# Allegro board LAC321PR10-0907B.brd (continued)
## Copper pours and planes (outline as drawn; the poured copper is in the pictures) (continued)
CHRGR_VIN on TOP: 45.01,118.9 41.85,118.9 41.74,118.79 41.74,118.35 41.69,118.3 41.12,118.3 41.01,118.19 41.01,117.63 41.14,117.5 41.14,117.5 41.21,117.43 42.5,117.43 42.61,117.32 42.61,116.56 42.37,116.31 42.37,115.17 42.48,115.06 44.71,115.06 44.75,115.1 44.75,115.35 45.07,115.67 45.07,118.85
CHRGR_VIN on TOP: 28.26,58.27 26.41,58.27 26.23,58.09 26.23,57.02 26.34,56.91 27.12,56.91 27.28,56.75 27.31,56.72 27.31,55.96 27.4,55.87 28.79,55.87 29.53,56.6 29.53,57.39 29.41,57.52 28.73,57.52 28.41,57.84 28.41,58.13
CHRGR_VIN on TOP: 13.35,56.89 13.44,56.97 13.44,58.41 13.64,58.61 13.64,59.26 13.45,59.45 11.37,59.45 11.27,59.35 11.27,58.58 11.27,58.5 10.79,58.02 10.79,57.39 11.3,56.89
CHRGR_VIN on BOTTOM: 22.07,55.85 21.23,56.69 20.11,56.69 19.27,55.85 11.87,55.85 11.44,56.28 11.44,56.31 11.22,56.52 11.22,59.23 15.54,63.55 25.27,63.55 29.48,59.33 29.48,57.12 28.21,55.85
CHRGR_VIN on IN2: 50.3,136.33 48.24,134.27 48.24,131.22 49.26,130.21 49.26,119.31 55.62,112.95 55.62,108.05 55.09,107.51 52.25,107.51 50.67,109.1 50.67,112.19 48.25,114.6 44.35,114.6 43.29,115.67 43.29,138.97 47.73,143.42 71.23,143.42 71.99,142.65 71.99,140.62 71.61,140.24 58.91,140.24 56.11,137.45 56.11,136.66 55.78,136.33
CHRGR_VIN on VCC: 23.2,55.79 22.21,56.78 22.21,90.73 23.84,92.36 47.46,92.36 54.21,99.12 54.21,110.55 54.57,110.9 60.94,110.9 60.94,92.72 54.99,86.77 36.07,86.77 30.59,81.29 30.59,56.02 30.36,55.79
CORE_FB on TOP (solid shape): 193.78,149 193.78,144.56 193.91,144.43 193.91,144.03 193.83,143.95 193.71,143.95 193.61,144.05 193.61,144.23 193.24,144.6 193.24,145.11 192.64,145.7 192.64,149 192.77,149.13 193.66,149.13
CPU_B+ on TOP (solid shape): 78.73,110.14 80.53,110.14 80.91,109.76 82.28,109.76 83.04,109 85.81,109 85.96,108.85 85.96,107.73 85.71,107.48 83.93,107.48 83.75,107.66 83.75,108.19 83.57,108.36 83.04,108.36 82.25,107.58 77.83,107.58 77.32,108.09 77.32,109.89 77.58,110.14 78.72,110.14
CPU_B+ on TOP (solid shape): 73.93,102.96 73.93,102.51 74.14,102.31 77.44,102.31 77.48,102.27 77.48,101.43 77.46,101.42 77.3,101.42 77,101.11 77,100.15 77.16,99.98 77.68,99.98 77.7,99.96 77.7,99.47 77.7,99.38 77.67,99.35 74.91,99.35 74.53,98.97 74.53,96.93 74.3,96.71 66.78,96.71 66.64,96.84 66.64,99.25 66.7,99.3 69.33,99.3 69.38,99.26 69.38,98.2 69.57,98.01 71.93,98.01 72.5,98.59 72.5,102.97 72.62,103.09 73.8,103.09
CPU_B+ on TOP: 77.96,117.95 77.96,120.43 78.34,120.81 80.05,120.81 80.31,120.56 82.02,120.56 82.4,120.18 85.45,120.18 85.58,120.05 85.58,119.03 85.32,118.78 83.67,118.78 83.37,119.08 83.37,119.54 83.32,119.59 82.56,119.59 82.43,119.46 82.43,118.14 81.77,117.48 81.77,117.17 81.69,117.09 78.82,117.09
CPU_B+ on BOTTOM: 81.51,120.68 82.4,119.79 82.4,103.23 76.77,97.59 72.88,97.59 72.73,97.75 72.73,119.64 73.77,120.68
CPU_B+ on IN1: 78.34,110.27 81.77,110.27 83.04,109 85.83,109 85.96,108.87 85.96,107.86 85.71,107.6 80.24,107.6 79.86,107.98 77.83,107.98 77.58,108.24 77.58,109.51
CPU_B+ on IN1: 85.58,120.05 85.58,119.03 85.32,118.78 83.42,118.78 82.78,118.14 79.74,118.14 79.36,118.52 78.85,118.52 77.96,119.41 77.96,119.88 78.25,120.18 85.45,120.18
CPUBST1 on TOP: 83.97,103.54 82.57,103.54 82.51,103.6 82.51,104.35 82.53,104.38 83.5,104.38 83.64,104.52 84.01,104.52 84.13,104.4 84.13,103.69
CPUDRVH1 on TOP: 83.17,108.24 83.55,108.24 83.64,108.15 83.64,107.59 84.12,107.1 84.12,105.93 84.02,105.82 83.8,105.82 83.67,105.95 83.67,106.46 82.91,107.22 82.91,107.98
CPUDRVL1 on TOP: 85.32,105.7 85.26,105.76 85.26,106.65 85.32,106.71 86.59,106.71 86.85,106.46 86.85,105.82 86.72,105.7
CPUSW1 on TOP (solid shape): 89.13,113.32 89.13,110.78 88.72,110.36 88.72,108.12 88.63,108.03 88.63,107.6 88.5,107.48 86.47,107.48 86.21,107.73 86.21,108.75 85.71,109.25 83.04,109.25 82.91,109.38 82.91,110.27 83.04,110.4 86.59,110.4 87.86,111.67 87.86,113.32 88.12,113.57 88.88,113.57
DCPDSW_1P0 on TOP: 135.41,106.89 135.82,106.89 136.1,106.61 137.88,106.61 138,106.48 138,105.77 137.92,105.68 137.31,105.68 136.94,106.05 135.77,106.05 135.52,106.31 135.21,106.31 135.19,106.28 135.11,106.28 135.03,106.36 135.03,106.48 135.11,106.56 135.11,106.71 135.13,106.74 135.26,106.74
ENVDD on TOP: 174.86,103.92 174.61,103.67 173.6,103.67 173.09,104.17 172.57,104.17 172.35,103.94 172.35,103.46 172.17,103.28 171.15,103.28 171.05,103.39 171.05,104.68 172.04,105.67 173.32,105.67 174.05,104.94 174.61,104.94 174.86,104.68
GTBST1 on TOP: 83.04,115.6 83.42,115.6 83.55,115.48 83.55,114.84 83.8,114.59 83.8,113.7 83.67,113.57 83.04,113.57 82.91,113.7 82.91,115.48
GTDRVH1 on TOP: 82.66,119.41 83.17,119.41 83.29,119.29 83.29,118.52 83.55,118.27 83.55,117 83.42,116.87 82.91,116.87 82.66,117.13 82.66,118.02 82.53,118.14 82.53,119.29
GTDRVL1 on TOP: 84.69,117.89 85.07,117.89 85.33,117.64 85.33,117.11 85.33,117.11 85.98,117.11 86.21,116.87 86.21,116.37 85.96,116.11 85.45,116.11 84.56,117 84.56,117.76
GTSW1 on TOP (solid shape): 88.33,125.12 88.33,121.53 88.3,121.49 88.3,120.35 88.22,120.28 87.51,120.28 87.41,120.18 87.41,119.9 87.56,119.74 88.3,119.74 88.35,119.69 88.35,118.73 88.27,118.65 86.34,118.65 86.15,118.84 86.15,119.99 85.71,120.43 82.66,120.43 82.53,120.56 82.53,121.45 82.66,121.57 85.53,121.57 86.85,122.89 86.85,125.14 87.04,125.34 88.11,125.34
JUSBC1_GND on TOP: outline of 112 points within 0.25,23.71 11.28,37.93
JUSBC2_GND on TOP: 0.25,10.07 0.25,11.54 0.34,11.71 0.52,11.77 1.3,11.77 1.3,11.78 4.79,11.78 5.63,11.29 6.25,12.03 6.25,14.09 7.54,14.09 7.72,13.93 7.78,13.69 7.81,13.63 7.87,13.62 7.95,13.63 8,13.66 8.02,13.72 8.03,13.84 8.1,13.95 8.13,14.01 8.1,14.06 8.07,14.09 8.25,14.09 8.25,19.19 8.02,19.19 8.01,19.28 8.04,19.36 8.03,19.43 7.97,19.47 7.92,19.48 7.86,19.48 7.79,19.46 7.77,19.39 7.78,19.29 7.77,19.19 6.25,19.19 6.25,20.98 5.63,21.72 4.79,21.23 1.5,21.23 1.33,21.31 1.25,21.48 1.25,23.66 7.6,23.66 9.38,21.88 10.9,21.88 11.28,21.5 11.28,10.45 10.9,10.07
JUSBC2_GND on IN1: 11.67,13.19 10.89,13.19 10.81,13.11 10.81,11.36 10.97,11.21 13.63,11.21 13.93,11.5 13.93,13.88 13.57,14.24 12.71,14.24
LG11 on TOP: 164.32,106.08 165.21,106.08 165.33,105.95 165.33,105.19 165.21,105.06 164.32,105.06 164.06,105.32 164.06,105.82
LG11 on BOTTOM: 168.13,114.41 169.45,114.41 169.65,114.21 169.65,113.19 169.14,112.68 168.26,112.68 168.13,112.81
MIC1_L on TOP (solid shape): 20.55,13.24 20.55,12.86 20.71,12.71 20.71,12.71 20.94,12.48 20.94,11.84 20.55,11.46 19.92,11.46 19.79,11.59 19.79,12.35 19.69,12.45 19.44,12.45 19.31,12.58 19.31,12.76 19.56,13.01 19.56,13.14 19.79,13.37 20.43,13.37
MIC1_L on IN2 (solid shape): 21.44,12.23 21.44,11.59 21.19,11.34 19.92,11.34 19.16,12.1 19.16,12.86 19.41,13.11 20.55,13.11
MIC1_L on TOP: 29.64,15.73 29.76,15.73 29.81,15.67 29.81,14.81 29.84,14.78 29.84,14.22 30.08,13.98 30.08,13.37 29.95,13.24 29.6,13.24 29.42,13.42 29.42,14.28 29.55,14.41 29.55,14.68 29.6,14.72 29.6,15.69
MIC1_L on IN2: 29.9,14.27 29.9,13.75 30.03,13.62 30.03,13.34 29.93,13.24 29.57,13.24 28.92,12.59 28.23,12.59 28.11,12.71 28.11,13.37 29.09,14.35 29.83,14.35
MIC1_R on IN2 (solid shape): 22.97,14.13 22.97,12.99 22.71,12.73 21.44,12.73 21.19,12.99 21.19,13.93 21.44,13.93 21.44,13.88 21.45,13.82 21.47,13.78 21.49,13.73 21.52,13.69 21.56,13.65 21.6,13.62 21.65,13.6 21.7,13.58 21.75,13.57 21.8,13.57 21.85,13.58 21.9,13.6 21.95,13.62 21.99,13.65 22.03,13.69 22.06,13.73 22.08,13.78 22.1,13.82 22.1,13.88 22.1,13.93 22.1,13.98 22.08,14.03 22.06,14.07 22.03,14.12 21.99,14.15 21.95,14.18 21.9,14.21 21.85,14.22 21.8,14.23 21.75,14.23 21.7,14.22 21.65,14.21 21.6,14.18 21.56,14.15 21.52,14.12 21.49,14.07 21.47,14.03 21.45,13.98 21.44,13.93 21.19,13.93 21.19,14.26 21.32,14.38 22.71,14.38
MIC1_R on TOP: 30.05,15.74 30.14,15.74 30.21,15.67 30.21,14.8 30.23,14.78 30.23,14.66 30.51,14.38 30.51,13.98 30.66,13.83 30.66,13.6 30.49,13.42 30.36,13.42 30.16,13.62 30.16,14 29.95,14.21 29.95,14.83 30,14.89 30,15.69
MIC1_R on TOP: 21.19,11.46 21.06,11.59 21.06,12.61 20.94,12.73 20.81,12.73 20.68,12.86 20.68,13.37 20.81,13.5 22.08,13.5 22.46,13.11 22.46,12.86 22.33,12.73 21.82,12.73 21.7,12.61 21.7,11.72 21.44,11.46
MIC1_R on IN2: 29.7,15.65 29.83,15.78 30.74,15.78 30.97,15.55 30.97,14.64 30.84,14.51 30.84,13.7 30.64,13.5 30.28,13.5 29.95,13.83 29.95,14.92 29.7,15.17
P_AGND on TOP: 176,122.21 176.26,121.95 177.27,121.95 177.78,121.45 177.78,121 177.96,120.82 178.61,120.82 178.67,120.76 178.67,120.15 178.61,120.09 177.97,120.09 177.88,120.18 177.25,120.18 177.07,120 176.69,120 176.26,120.43 174.99,120.43 174.87,120.31 174.46,120.31 174.43,120.28 174.43,119.87 174.22,119.67 172.95,119.67 172.7,119.92 172.7,120.81 172.32,121.19 172.32,121.83 172.57,122.08 173.21,122.08 173.46,121.83 173.46,120.81 173.59,120.68 174.32,120.68 174.36,120.72 174.36,120.93 174.35,120.94 174.35,121.95 174.61,122.21
P_AGND on GND2: 166.2,115.22 160,121.42 160,126.17 162.77,128.94 169.55,128.94 177.65,120.83 177.65,119.65 173.84,115.84 173.84,115.33 173.74,115.22
P_AGND on GND3: 164.55,115.73 160.13,120.15 160.13,126.04 162.9,128.81 169.42,128.81 177.27,120.96 177.27,119.39 173.61,115.73
P_AGND_1 on IN3: 69.2,120.43 78.97,120.43 79.36,120.05 79.36,117.51 78.97,117.13 72.75,117.13 71.86,116.24 71.86,113.83 72.37,113.32 72.37,110.27 71.61,109.51 71.61,107.48 74.91,104.17 74.91,101.25 72.37,98.71 67.29,98.71 66.91,99.09 66.91,100.49 67.67,101.25 67.67,118.91
PLL_COMP1 on TOP (solid shape): 195.1,141.41 195.1,141.08 195.31,140.88 195.69,140.88 196.68,139.89 196.76,139.89 197.08,139.56 197.08,139.2 197.06,139.17 195.9,139.17 195.85,139.23 195.85,139.95 194.82,140.98 194.82,141.41 194.88,141.46 195.05,141.46
PLL_COMP2 on TOP (solid shape): 194.72,141.38 194.72,140.7 195.63,139.79 195.63,139.13 195.61,139.1 194.67,139.1 194.67,139.1 194.49,139.1 194.42,139.18 194.42,141.41 194.47,141.46 194.65,141.46
PLL_VDD on TOP (solid shape): 194.32,141.38 194.32,139.25 194.16,139.1 193.66,139.1 193.65,139.1 193.56,139.1 193.49,139.17 193.49,139.92 194.04,140.47 194.04,141.38 194.11,141.46 194.24,141.46
REG5 on BOTTOM: 171.18,124.37 170.29,124.37 167.11,121.19 167.11,120.94 167.24,120.81 167.49,120.81 170.54,123.86 171.18,123.86 171.3,123.99 171.3,124.24
REG33 on TOP: 172.45,123.22 175.88,123.22 176,123.1 176,122.46 175.88,122.33 174.99,122.33 174.86,122.46 172.45,122.46 172.32,122.59 172.32,123.1
RING2 on TOP (solid shape): 19.67,12.23 19.67,9.69 19.77,9.58 19.77,9.53 19.79,9.53 19.79,9.18 19.77,9.15 18.8,9.15 18.78,9.18 18.78,12.23 18.9,12.35 19.54,12.35
RING2 on GND1 (solid shape): 21.82,6.97 21.82,5.67 21.77,5.62 20.55,5.62 20.55,7.15 21.65,7.15
RING2 on TOP: 21.72,6.85 21.9,6.66 21.9,5.44 21.8,5.34 20.69,5.34 20.55,5.47 20.55,6.64 20.76,6.85
RING2 on IN2: 18.52,9.56 19.67,9.56 19.73,9.5 19.98,9.5 22.21,7.27 22.21,6.13 21.82,5.75 19.03,5.75 18.27,6.51 18.27,9.3
RING2 on GND4: 20.55,6.31 20.55,6.84 20.73,7.02 22.15,7.02 22.46,6.71 22.46,6.44 22.15,6.13 20.73,6.13
SASWS on TOP (solid shape): 82.02,102.78 82.02,100.36 81.26,99.6 81.26,97.32 80.75,96.81 78.85,96.81 77.7,97.95 75.2,97.95 75.12,98.03 75.12,99.05 75.16,99.09 77.7,99.09 79.36,100.74 79.36,101.89 79.61,102.14 80.75,102.14 80.88,102.27 80.88,102.78 81.13,103.03 81.77,103.03
SD_REG2 on TOP: 25.34,78.28 26.13,78.28 26.18,78.23 26.18,78.13 26.13,78.08 26.13,77.31 24.5,75.69 23.84,75.69 23.72,75.81 23.72,76.32 23.84,76.45 24.23,76.45 25.24,77.47 25.24,78.18
SLEEVE on TOP (solid shape): 22.46,12.35 22.46,11.46 22.33,11.34 22.33,11.27 22.31,11.2 22.31,11.13 22.31,10.75 22.33,10.72 22.33,10.57 22.59,10.32 22.59,9.18 22.56,9.15 21.59,9.15 21.57,9.18 21.57,11.35 21.82,11.6 21.82,12.35 21.95,12.48 22.33,12.48
SLEEVE on GND1 (solid shape): 20.3,5.62 19.08,5.62 18.78,5.93 18.78,6.84 19.08,7.15 20.3,7.15
SLEEVE on TOP: 18.9,6.76 20.17,6.76 20.43,6.51 20.43,5.48 20.2,5.25 18.94,5.25 18.78,5.41 18.78,6.64
SLEEVE on BOTTOM: 23.86,10.7 24.24,10.32 24.24,5.88 23.86,5.49 18.9,5.49 18.52,5.88 18.52,7.27 19.16,7.91 20.17,7.91 21.06,8.8 21.06,10.45 21.32,10.7
SPK_L+ on TOP: 21.04,93.15 20.98,93.21 20.98,93.78 21.06,93.87 24.03,93.87 24.13,93.77 24.9,93.77 24.95,93.83 25.51,93.83 25.52,93.81 25.52,93.03 25.49,93 24,93 23.74,93.26 22.8,93.26 22.69,93.15
SPK_L+ on IN1: 10.31,97.18 11.94,97.18 12.1,97.02 12.1,96.6 12.03,96.54 10.39,96.54 10.19,96.74 10.19,97.06
SPK_L+ on IN1: 21.56,93.76 20.85,93.76 20.09,93 20.09,92.63 20.34,92.38 20.59,92.38 21.36,93.14 21.52,93.14 21.58,93.2 21.58,93.73
SPK_L+_L on TOP (solid shape): 206.17,116.16 206.17,115.34 205.6,114.78 204.78,114.78 204.64,114.92 204.64,115.11 204.62,115.13 204.62,115.29 204.62,115.29 204.62,116.17 204.66,116.21 206.12,116.21
SPK_L+_L on TOP: 26.75,92.96 26.96,93.16 26.96,93.92 26.84,94.04 25.83,94.04 25.76,93.97 25.76,93.02 25.82,92.96
SPK_L+_L on BOTTOM: 26.75,94.05 25.5,94.05 25.39,93.94 25.39,93.07 25.56,92.9 26.73,92.9 26.87,93.04 26.87,93.94
SPK_L+_L on BOTTOM: 40.48,103.37 40.45,103.41 40.45,105.04 40.51,105.1 40.89,105.1 41.19,104.79 41.19,103.4 41.17,103.37
SPK_L+_L on GND3: 204.78,116.23 203.84,116.23 203.61,116.01 203.61,115.3 203.95,114.96 204.93,114.96 205.12,115.14 205.12,115.89
SPK_L+_L on GND3: 42.12,106.07 42.16,106.04 42.16,105.23 41.46,104.53 41.46,104.08 41.36,103.99 40.75,103.99 40.57,104.17 40.57,104.96 41.68,106.07
SPK_L- on TOP: 21,92.77 20.98,92.75 20.98,92.1 21.03,92.05 22.17,92.05 22.3,91.91 25.5,91.91 25.53,91.94 25.53,92.7 25.51,92.72 24.65,92.72 24.47,92.54 22.79,92.54 22.56,92.77
SPK_L- on IN1: 21.08,92.71 21.55,92.71 21.63,92.62 21.63,92.06 21,91.42 20.69,91.42 20.33,91.79 20.33,91.96
SPK_L- on IN1: 11.23,96.24 9.56,96.24 9.43,96.11 9.43,95.02 9.57,94.88 10.18,94.88 11.3,96 11.3,96.17
SPK_L-_L on TOP: 25.74,92.73 26.82,92.73 27.08,93 27.08,93.62 27.09,93.62 27.09,93.84 27.77,94.52 28.21,94.52 28.32,94.41 28.32,93.97 27.96,93.61 27.96,91.88 27.76,91.69 25.88,91.69 25.69,91.88 25.69,92.68
SPK_R+ on TOP (solid shape): 252.23,133.45 252.23,133.14 252.1,133.02 251.21,133.02 251.06,133.17 251.06,133.18 249.95,134.29 247.41,134.29 247.16,134.54 247.16,135.27 247.3,135.41 250.27,135.41
SPK_R+ on IN1 (solid shape): 245.51,135.41 247.42,135.41 247.47,135.36 247.47,134.69 247.37,134.59 245.27,134.59 243.34,136.53 243.34,137.13 243.37,137.17 243.75,137.17
SPK_R+ on TOP: 242.16,137.54 242.54,137.54 242.67,137.41 242.67,137.22 242.74,137.14 243.56,137.14 243.62,137.09 243.62,136.57 243.56,136.51 242.7,136.51 242.57,136.64 242.06,136.64 242.03,136.67 242.03,137.41
SPK_R+_L on TOP: 241.9,137.42 241.9,136.72 241.83,136.65 241.14,136.65 240.96,136.83 240.96,137.91 241.07,138.02 242.01,138.02 242.12,137.92 242.12,137.63
SPK_R+_L on TOP: 210.89,124.63 212.4,124.63 212.5,124.53 212.5,123.59 212.36,123.45 210.98,123.45 210.78,123.66 210.78,124.52
SPK_R+_L on BOTTOM: 241.81,138.08 239.83,138.08 239.66,137.9 239.66,137.37 239.69,137.33 242.02,137.33 242.06,137.37 242.06,137.84
SPK_R+_L on BOTTOM: 212.16,125.05 212.16,125.23 212.62,125.69 212.78,125.69 212.95,125.52 212.95,124.86 212.32,124.24 212.32,123.74 212.11,123.53 211.8,123.53 211.62,123.71 211.62,124.51
SPK_R- on TOP (solid shape): 251.09,132.89 252.1,132.89 252.36,132.63 252.36,132.25 252.1,132 250.7,132 249.54,133.16 249.53,133.16 249.46,133.24 247.38,133.24 247.23,133.38 247.23,133.93 247.4,134.1 249.87,134.1
SPK_R- on IN1 (solid shape): 245.44,134.05 247.46,134.05 247.62,133.88 247.62,133.33 247.45,133.16 244.95,133.16 243.12,134.99 243.12,135.71 243.27,135.85 243.63,135.85
SPK_R- on TOP: 242.87,135.89 243.55,135.89 243.68,135.76 243.68,133.89 243.59,133.8 242.42,133.8 242.38,133.84 242.38,135.4
SPK_R-_L on TOP: 241.42,136.52 241.89,136.52 241.89,136.52 242.53,136.52 242.68,136.37 242.68,135.91 242.23,135.46 242.23,133.83 242.2,133.8 241.36,133.8 241.14,134.01 241.14,136.24
SW4 on TOP (solid shape): 160.13,118.65 160.13,117.76 160.64,117.25 163.05,117.25 163.43,116.87 163.43,116.37 163.18,116.11 160.38,116.11 158.93,114.66 158.93,114.02 158.81,113.9 157.44,113.9 157.33,114 157.33,116.87 158.48,118.02 158.48,118.91 158.73,119.16 159.62,119.16
SW5 on TOP (solid shape): 183.75,134.02 183.75,131.24 184.41,130.58 184.41,128.67 184.17,128.43 180.57,128.43 179.94,129.07 179.08,129.07 178.8,129.34 178.8,130.08 178.92,130.21 179.43,130.21 179.69,130.46 179.69,130.97 179.81,131.1 182.35,131.1 182.73,131.48 182.73,134.02 182.86,134.15 183.62,134.15
SW6 on TOP (solid shape): 177.81,118.26 177.81,117.78 177.81,117.78 177.81,117.66 177.49,117.34 177.49,117.34 177.46,117.31 177.46,117.08 177.45,117.04 177.45,116.99 177.45,116.94 177.45,116.89 177.46,116.85 177.49,116.78 177.49,116.64 177.64,116.49 180.96,116.49 181.72,117.25 187.31,117.25 187.56,117 187.56,115.98 187.05,115.48 186.42,115.48 185.53,114.59 182.23,114.59 181.34,115.48 177.5,115.48 177.07,115.91 176.93,115.91 176.72,116.12 176.72,117.64 177.04,117.96 177.04,118.27 177.11,118.34 177.73,118.34
SW7 on TOP (solid shape): 180.07,124.75 180.07,124.74 180.15,124.66 180.15,121.89 180.09,121.83 179.15,121.83 179.05,121.93 179.05,122.71 178.42,123.35 176.5,123.35 176.42,123.43 176.42,124.27 177.02,124.87 179.94,124.87
SW8 on TOP (solid shape): 166.35,134.91 166.35,133.1 166.2,132.95 164.63,132.95 163.66,133.92 163.52,133.92 163.43,134.01 163.43,134.97 163.62,135.16 166.1,135.16
SW9 on TOP (solid shape): 174.73,133 174.73,131.61 174.35,131.22 172.19,131.22 171.94,131.48 171.94,132.49 172.19,132.75 172.95,132.75 173.59,133.38 174.35,133.38
SW10 on TOP (solid shape): 155.68,128.56 155.68,125.64 155.94,125.38 157.21,125.38 157.46,125.13 157.46,121.88 157.36,121.78 155.48,121.78 155.3,121.95 155.3,124.62 154.54,125.38 154.54,128.25 154.48,128.31 154.48,128.78 154.53,128.83 155.41,128.83
SW11 on TOP (solid shape): 159.37,108.75 159.37,108.24 159.75,107.86 162.79,107.86 163.35,108.41 164.32,108.41 164.32,108.41 164.48,108.41 164.57,108.31 164.57,107.88 164.47,107.78 164.06,107.78 164.06,107.22 163.81,106.97 163.12,106.97 162.74,106.59 159.62,106.59 159.37,106.33 159.37,104.05 159.24,103.92 158.35,103.92 158.1,104.17 158.1,104.68 156.7,106.08 156.7,108.87 157.08,109.25 158.86,109.25
SW11 on IN3: 163.87,108.67 165.21,108.67 165.21,108.16 164.59,107.54 163.58,107.54 163.42,107.7 163.42,108.21
SW12 on TOP: 169.44,117.42 169.65,117.64 169.65,119.63 169.41,119.88 169.06,119.88 168.64,120.3 168.64,120.56 168.76,120.68 168.89,120.68 169.02,120.56 169.4,120.56 169.91,120.05 170.92,120.05 171.39,119.58 171.39,117.42 171.6,117.22 172.07,117.22 172.19,117.09 172.19,116.25 172.05,116.11 168.46,116.11 168.26,116.31 168.26,117.28 168.4,117.42
TBT_SVR_IND on TOP: 20.8,30.01 20.98,30.18 20.98,30.79 21.05,30.87 21.24,30.87 21.33,30.78 21.33,30.61 21.44,30.5 21.57,30.5 21.58,30.51 21.7,30.51 21.82,30.39 21.82,29.78 21.05,29 21.05,27.52 20.82,27.29 20.82,25.7 20.01,24.89 19.03,24.89 18.76,25.15 18.76,28.46 18.88,28.58 19.05,28.58 20.49,30.01
TBTA_DC_SS on TOP: 41.74,114.59 43.94,114.59 44.28,114.25 44.28,111.88 44.79,111.37 44.79,109.79 44.04,109.04 41.61,109.04 41.48,109.17 41.48,114.33
TBTA_DCIN on TOP: 43.64,105.06 43.64,105.06 43.64,104.05 43.58,103.98 43.15,103.98 43.12,104.01 43.12,104.75 42.93,104.94 42.49,104.94 42.22,104.67 41.06,104.67 40.97,104.76 40.97,105.83 41.09,105.95 41.49,105.95 41.51,105.95 41.72,106.16 41.72,106.74 41.62,106.85 41.27,106.85 41.16,106.95 41.16,108.54 41.29,108.68 43.34,108.68 43.47,108.54 43.47,107.58 43.64,107.41
TBTA_DCIN on IN3: 45.03,122.59 46.08,123.64 46.43,123.98 46.43,129.95 47.02,130.54 47.02,132.44 47,132.47 47,132.65 47.46,133.11 47.46,135.51 46.99,135.98 43.9,135.98 42.69,134.77 42.69,125.24 42.17,124.71 42.17,110.96 40.54,109.34 40.54,107 40.67,106.87 43.55,106.87 43.76,107.08 43.76,107.88 45.91,110.03 45.91,117.85 44.54,119.22 44.54,122.1
TBTA_VBUS on TOP (solid shape): 19.17,50.11 19.17,47.94 18.95,47.72 17.87,47.72 17.83,47.77 17.83,49.11 17.53,49.41 17.53,50.34 17.57,50.38 18.9,50.38
TBTA_VBUS on IN3 (solid shape): 38.59,41.44 38.59,39.73 38.13,39.28 37.45,39.28 37.08,39.64 37.08,40.53 38.13,41.59 38.44,41.59
TBTA_VBUS on TOP: 36.91,42.86 38.5,42.86 38.74,42.62 38.74,40.99 38.73,40.98 38.73,40.58 38.6,40.44 37.26,40.44 36.6,41.11 36.6,42.54
TBTA_VBUS on TOP: 40.75,104.03 40.75,102.19 41.07,101.87 43.68,101.87 43.75,101.94 43.75,103.73 43.64,103.83 43.07,103.83 43.01,103.9 43.01,104.69 42.88,104.82 42.55,104.82 42.25,104.53 41.25,104.53
TBTA_VBUS on TOP: 19.91,54.9 21.19,54.9 21.44,54.64 21.44,53.12 21.19,52.87 20.55,52.87 19.69,53.73 19.69,54.68
TBTA_VBUS on TOP: 12.93,36.27 13.16,36.05 14.73,36.05 15.16,36.48 15.73,36.48 15.98,36.74 15.98,37.44 15.8,37.62 15.62,37.62 15.59,37.65 15.59,38.13 15.49,38.23 13.3,38.23 12.93,37.87
TBTA_VBUS on BOTTOM: 37.56,42.07 38.03,42.07 38.27,41.83 38.27,40.53 38.16,40.42 37.79,40.42 37.47,40.74 37.47,41.98
TBTA_VBUS on BOTTOM: 21.29,21.08 19.69,21.08 19.55,21.22 19.55,21.95 19.98,22.38 21.59,22.38 21.72,22.25 21.72,21.51
TBTA_VBUS on BOTTOM: 23.18,21.29 24.34,21.29 24.49,21.45 24.49,23.12 24.42,23.2 23.43,23.2 23.08,22.86 23.08,21.39
TBTA_VBUS on IN1: 10.22,39.02 12.43,39.02 13.7,37.75 13.7,34.45 10.52,31.28 7.22,31.28 6.97,31.53 6.97,32.42 7.73,33.18 7.73,36.53
TBTA_VBUS on GND1: 12.79,37.71 12.06,37.71 11.64,38.12 11.64,41.04 11.99,41.39 12.67,41.39 12.98,41.07 12.98,37.89
TBTA_VBUS on GND1: 15.98,48.22 15.98,48.37 16.8,49.18 17.96,49.18 18.4,48.75 18.4,48.09 17.96,47.66 16.54,47.66
TBTA_VBUS on IN2: 19.28,55.66 20.17,55.66 20.68,55.15 20.68,52.74 20.55,52.61 20.55,51.72 20.17,51.34 20.17,49.56 18.01,47.4 16.49,47.4 16.11,47.79 16.11,48.29 17.63,49.82 17.63,49.94 18.27,50.58 18.27,54.64
TBTA_VBUS on IN2: 9.38,37.5 9.71,37.17 9.71,36.49 10.62,35.58 10.62,31.04 10.73,30.93 10.73,29.51 10.84,29.39 10.84,26.64 10.52,26.32 8.74,26.32 7.95,27.11 7.95,31.33 7.74,31.54 7.11,31.54 6.97,31.68 6.97,33.05 7.73,33.82 7.73,36.63 8.59,37.5
TBTA_VBUS on IN3: 18.78,22.14 20.1,22.14 20.3,21.94 20.3,21.22 20.21,21.13 18.82,21.13 18.65,21.29 18.65,22.02
TBTA_VBUS on IN3: 23.37,22.56 23.37,23.46 23.51,23.6 25.37,23.6 25.42,23.55 25.42,22.5 25.26,22.34 23.58,22.34
TBTA_VBUS on IN3: 17.18,49.1 14.78,49.1 14.04,48.36 14.04,43.37 11.99,41.32 11.99,39.33 13.11,38.22 15.8,38.22 16,38.42 16,42.06 17.4,43.46 17.4,48.88
TBTA_VBUS on IN3: 7.07,28.2 6.98,28.29 6.98,29.06 6.97,29.07 6.97,29.99 7.44,29.99 7.44,31.05 6.97,31.05 6.97,32.15 7.23,32.4 9.33,32.4 9.53,32.21 9.53,29.54 9.26,29.27 9.26,28.48 8.98,28.2
TBTA_VBUS on GND4: 11.55,41.44 12.72,41.44 12.96,41.19 12.96,39.89 12.58,39.5 11.71,39.5 11.44,39.76 11.44,41.33
TBTA_VBUS on VCC: outline of 122 points within 2.57,36.33 45.7,140.75
TBTA_VBUS_L on TOP: 14.35,51.4 14.24,51.29 14.24,51.09 14.09,50.93 13.87,50.93 13.79,50.86 13.77,50.82 13.77,50.58 13.86,50.49 14.01,50.49 14.19,50.31 14.19,49.21 14.38,49.02 16.4,49.02 16.67,49.29 16.67,51.51 16.4,51.77 14.87,51.77 14.5,51.4
TBTA_VBUS_L on IN2: 13.37,55.41 13.37,55.47 13.51,55.61 14.18,55.61 15.11,54.68 16.32,54.68 17.08,53.92 17.08,50.19 15.72,48.83 14.44,48.83 14.12,49.15 14.12,51.56 14.59,52.03 14.59,52.74 13.06,54.26 13.06,55.1
TBTB_DC_SS on TOP (solid shape): 49.64,114.14 49.64,108.96 49.48,108.79 47.05,108.79 46.89,108.95 46.89,110.55 46.63,110.82 46.63,111.82 46.41,112.03 45.69,112.03 45.56,112.16 45.56,113.48 45.64,113.56 46.35,113.56 47.06,114.27 49.52,114.27
TBTB_DCIN on TOP: 51.96,107.93 51.96,106.92 51.5,106.46 50.3,106.46 49.44,105.6 49.44,104.83 49.27,104.66 47.53,104.66 47.33,104.46 47.33,103.93 47.28,103.88 46.76,103.88 46.63,104.01 46.63,107.89 47.47,108.73 48.66,108.73 48.96,108.43 48.96,107.22 49.03,107.16 49.4,107.16 50.29,108.05 51.85,108.05
TBTB_VBUS on TOP (solid shape): 49.67,104.36 49.67,103.97 49.6,103.89 49.6,103.89 49.57,103.86 49.57,102.23 49.22,101.87 46.84,101.87 46.68,102.04 46.68,103.63 46.79,103.74 47.34,103.74 47.45,103.86 47.45,104.38 47.58,104.51 49.53,104.51
TBTB_VBUS on TOP: 18.55,54.48 19.46,54.48 19.58,54.36 19.58,53.75 20.39,52.94 20.39,52.46 20.31,52.38 19.72,52.38 19.31,52.79 18.71,52.79 18.36,53.14 18.36,54.29
TBTB_VBUS on TOP: 32.69,47.82 32.69,45.18 32.43,44.92 31.32,44.92 31,45.24 31,47.79 31.2,47.99 32.52,47.99
TBTB_VBUS on TOP: 35.91,41.18 35.03,41.18 34.65,41.56 34.65,43.98 35.29,44.61 35.29,45.5 35.54,45.75 36.3,45.75 36.42,45.64 36.42,41.69
TBTB_VBUS on TOP: 14.12,17.9 13.21,17.9 13.11,18 13.11,20.05 13.37,20.3 14.14,20.3 14.27,20.18 14.27,18.05
TBTB_VBUS on BOTTOM: 36.68,46.01 36.68,44.86 36.18,44.36 35.16,44.36 30.97,48.55 29.44,48.55 29.19,48.8 29.19,50.2 29.44,50.45 32.24,50.45
TBTB_VBUS on IN1: 31.1,49.25 31.99,49.25 32.04,49.2 32.04,46.28 31.86,46.11 30.43,46.11 29.4,47.14 29,47.54 28.74,47.8 28.74,49.19 29.18,49.63 30.73,49.63 30.85,49.5 30.85,49.48 30.92,49.33 31.08,49.26
TBTB_VBUS on GND1: 31.26,62.9 31.08,62.72 30.54,62.72 30.09,63.17 30.09,63.86 30.27,64.04 30.71,64.04 31.26,63.5
TBTB_VBUS on GND1: 28.23,50.58 29.52,50.58 29.95,50.15 29.95,48.98 29.9,48.93 28.86,48.93 27.92,49.87 27.92,50.27
TBTB_VBUS on IN2: 8.36,23.02 8.36,19.97 7.09,18.7 7.09,17.19 7.64,17.19 8,16.83 8,13.23 8.74,12.48 12.79,12.48 13.58,13.27 13.58,15.54 14.2,16.16 14.2,23.58 13.67,24.11 11.41,24.11 11.28,23.99 11.28,23.64 11.22,23.58 8.92,23.58
TBTB_VBUS on IN3: 10.62,35.61 10.15,36.08 10.15,42.37 6.04,46.48 6.04,47.15 5.06,48.13 5.06,50.96 7.45,53.34 11.79,53.34 12.17,52.97 12.17,44.49 13.19,43.47 13.19,42.69 12.07,41.58 12.07,39.06 13.07,38.06 13.07,36.48 14.33,35.22 14.33,15.65 13.07,14.4 7.46,14.4 6.97,14.89 6.97,15.91 7.22,16.16 7.22,16.92 6.97,17.18 6.97,18.7 8.24,19.97 8.24,23.53 10.62,25.92
TBTB_VBUS on IN3: 29.62,55.11 30.47,55.11 30.63,54.96 30.63,54.08 30.42,53.88 29.7,53.88 29.51,54.07 29.51,55
TBTB_VBUS on IN3: 30.12,63.86 30.91,63.86 31.06,63.71 31.06,62.3 30.98,62.23 30.07,62.23 29.91,62.38 29.91,63.66
TBTB_VBUS on GND4: 28.1,49.44 27.79,49.74 27.79,50.91 27.97,51.09 30.03,51.09 30.71,50.4 30.71,49.87 30.28,49.44
TBTB_VBUS on VCC: 23.84,49.69 22.18,51.34 12.66,51.34 12.02,51.98 8.24,51.98 8.24,97.72 10.5,99.98 40.35,99.98 46.06,105.7 49.15,105.7 49.64,105.21 49.64,103.52 43.31,97.19 13.46,97.19 11.66,95.39 11.66,58.53 12.25,57.95 21.34,57.95 21.7,57.59 21.7,56.57 22.99,55.28 31.63,55.28 31.98,54.92 31.98,50.05 31.63,49.69
TBTB_VBUS_L on TOP: 27.13,50.6 27.2,50.68 27.42,50.68 27.57,50.83 27.57,51.04 27.69,51.15 27.83,51.15 28.25,51.56 29.87,51.56 30,51.43 30,51.06 30.6,50.45 30.66,50.45 30.87,50.24 30.94,50.06 31.12,50 31.2,49.92 32.47,49.92 32.65,49.74 32.65,48.47 32.47,48.29 30.89,48.29 30.77,48.42 30.77,48.9 30.76,48.9 30.76,48.99 30.57,49.18 29.23,49.18 29.14,49.27 28.32,49.27 27.82,49.77 27.69,49.77 27.62,49.84 27.62,50.05 27.41,50.26 27.17,50.26 27.1,50.32 27.1,50.57
UF_AVDD_2.8V on TOP: 85.63,129.7 83.5,129.7 83.39,129.6 83.39,129.24 82.78,128.63 82.78,128.11 82.87,128.02 84.18,128.02 84.82,128.66 85.52,128.66 85.71,128.85 85.71,129.62
UF_AVDD_2.8V on TOP: 113.13,130.46 112.35,130.46 112.14,130.26 112.14,129.58 112.2,129.52 112.72,129.52 112.86,129.38 113.42,129.38 113.66,129.14 114.02,129.14 114.05,129.17 114.05,129.54
UF_DVDD_1.2V on TOP: 111.28,130.09 109.08,130.09 108.77,129.79 108.77,127.25 108.81,127.22 109.35,127.22 109.38,127.25 109.38,129.06 109.52,129.2 111.29,129.2 111.35,129.26 111.35,130.03
UF_VDD_1.8V on TOP: 188.2,143.5 189.47,143.5 189.61,143.37 189.61,142.96 189.58,142.92 189.11,142.92 189.02,142.83 189.02,142.41 188.96,142.36 188.11,142.36 188.04,142.43 188.04,143.34
VBOS on TOP (solid shape): 75.52,138.87 75.52,137.98 76.31,137.19 76.31,136.3 76.05,136.05 74.53,136.05 74.26,136.32 74.26,137.33 74.15,137.45 73.69,137.45 73.32,137.08 73.32,135.54 72.82,135.03 71.55,135.03 71.32,135.26 71.32,135.83 71.08,136.08 68.92,136.08 68.84,136.15 68.84,137.83 68.64,138.03 68.64,138.93 68.8,139.1 70.33,139.1 70.51,138.92 70.51,137.96 70.69,137.78 71.05,137.78 71.58,138.31 71.58,139 71.76,139.17 75.22,139.17
VBOS on TOP: 49.41,140.98 49.6,140.79 49.6,139.72 50.36,138.96 50.36,136.52 50.65,136.23 50.65,135.58 50.61,135.54 50.11,135.54 50.06,135.59 50.06,136.04 49.43,136.66 49.43,138.15 49.07,138.51 48.37,138.51 48.2,138.68 48.2,139.09 48.29,139.19 48.29,140.9 48.38,140.98
VCM_OUT_2.8V on TOP: 198.26,148.36 196.43,148.36 196.29,148.22 196.29,147.24 196.58,146.94 197.29,146.94 197.46,146.77 197.46,146.38 197.5,146.35 197.88,146.35 197.93,146.4 197.93,147.02 198.3,147.38 198.3,148.33
VCM_OUT_2.8V on BOTTOM: 142.35,137.57 143.87,137.57 144.13,137.32 144.13,135.8 144,135.67 142.47,135.67 142.22,135.92 142.22,137.45
WF_AVDD_2.8V on TOP: 190.84,141.09 188.92,141.09 188.72,141.28 187.77,141.28 187.63,141.14 187.63,140.41 188.08,139.96 190.77,139.96 190.96,140.15 190.96,140.96
WF_DOVDD_1.8V on TOP: 188.08,145.38 189.02,145.38 189.46,144.95 189.56,144.95 189.68,144.82 189.68,144.45 189.77,144.37 189.82,144.37 190.45,143.74 190.91,143.74 190.97,143.68 190.97,142.81 190.85,142.69 190.22,142.69 189.71,143.2 189.71,143.38 189.07,144.02 189.07,144.44 189.07,144.54 189.06,144.56 188.13,144.56 188.05,144.63 188.05,145.35
N11072906 on TOP: 164.95,130.84 165.33,130.46 166.99,130.46 167.28,130.76 167.28,130.91 167.39,131.02 167.93,131.02 168,130.95 168,129.57 167.75,129.32 165.08,129.32 164.7,129.7 164.32,129.7 164.15,129.87 164.15,130.73 164.26,130.84
N14367233 on TOP: 182.48,134.17 182.48,131.48 182.35,131.35 180.96,131.35 180.7,131.61 180.7,132.37 180.57,132.49 179.05,132.49 178.92,132.62 178.92,133.51 178.67,133.76 177.57,133.76 177.15,134.18 177.15,135.45 177.25,135.56 178.56,135.56 179.05,136.05 182.73,136.05 182.99,135.8 182.99,135.17 182.64,134.82 182.64,134.33
N14384859 on TOP: 176,115.73 177.02,115.73 177.4,115.35 180.19,115.35 180.32,115.22 180.32,114.21 180.07,113.95 179.3,113.95 178.42,113.06 178.42,112.17 177.83,111.59 177.83,110.82 177.7,110.69 177.21,110.69 176.7,110.18 175.91,110.18 175.88,110.22 175.88,115.6
N14433412 on TOP (solid shape): 158.98,128.56 158.98,127.29 159.24,127.03 160.89,127.03 160.89,126.3 160.86,126.27 156.7,126.27 156.44,126.02 156.44,125.64 155.94,125.64 155.94,128.53 156.09,128.68 158.86,128.68
N15844647 on TOP: 59.12,134.21 59.1,134.24 59.1,134.61 58.16,135.55 58.16,137.62 58.38,137.85 59.19,137.85 59.29,137.75 59.29,137.36 59.29,137.35 59.29,137.03 60.26,136.06 60.26,135.83 60.36,135.73 60.72,135.73 61.06,135.39 61.06,134.24 61.03,134.21
N16003749 on TOP: 48.31,118.89 48.64,118.56 50.33,118.56 50.46,118.44 50.46,116.33 50.45,116.31 46.1,116.31 45.98,116.44 45.98,118.83 46.05,118.89
N16035665 on TOP (solid shape): 153,130.36 153,129.38 152.81,129.19 150.09,129.19 149.84,129.45 149.84,130.34 150.09,130.59 152.77,130.59
N16039304 on TOP: 161.83,104.88 161.91,104.81 161.91,103.92 161.52,103.54 160.13,103.54 159.87,103.79 159.87,105.23 160.04,105.39 160.83,105.39 161.34,104.88
N16047467 on TOP (solid shape): 87.48,114.71 87.48,112.05 87.23,111.79 86.59,111.79 86.34,112.05 86.34,114.59 86.59,114.84 87.36,114.84
N16068697 on TOP: 84.63,125.36 86.4,125.36 86.52,125.24 86.52,123.95 86.39,123.82 85.17,123.82 84.53,124.46 84.53,125.26
N16073644 on TOP (solid shape): 80.75,104.05 80.75,102.52 80.63,102.4 79.36,102.4 79.23,102.52 79.23,103.03 78.72,103.54 78.72,104.05 78.97,104.3 80.5,104.3
N16216870 on TOP (solid shape): 84.82,102.71 84.82,101.44 84.69,101.32 82.66,101.32 82.53,101.44 82.53,102.71 82.78,102.97 84.56,102.97
N16803391 on TOP (solid shape): 193.5,141.77 193.5,141.64 193.45,141.59 192.89,141.59 192.79,141.49 192.79,141.03 192.79,141.03 192.79,140.87 192.39,140.47 192.39,140.24 192.26,140.11 191.62,140.11 191.5,140.24 191.5,141 191.75,141.26 192.21,141.26 192.3,141.35 192.36,141.35 192.36,141.41 192.82,141.87 193.4,141.87
N16803911 on TOP: 197.34,145.89 197.21,145.76 196.97,145.76 196.73,145.52 196.73,144.96 196.37,144.61 195.23,144.61 194.8,144.18 194.8,144.05 194.67,143.92 194.54,143.92 194.42,144.05 194.42,144.56 194.8,144.94 194.93,144.94 195.18,145.19 195.94,145.19 196.02,145.28 196.02,146.05 196.22,146.25 196.22,146.59 196.35,146.72 197.26,146.72 197.34,146.64
N16803963 on TOP: 192.39,143.5 192.39,143.29 193.02,142.65 193.48,142.65 193.53,142.6 193.53,142.43 193.45,142.35 192.94,142.35 192.64,142.65 191.5,142.65 191.37,142.78 191.37,143.54 191.46,143.63 192.25,143.63
N16823076 on TOP: 17.39,22.89 20.26,22.89 20.38,22.78 20.38,22.22 19.51,21.35 19.51,20.89 19.28,20.67 17.36,20.67 17.22,20.8 17.22,22.73
N17240153 on TOP: 192.77,105.95 193.78,105.95 193.91,105.82 193.91,104.3 193.15,103.54 192.39,103.54 192.26,103.67 192.26,104.94 192.64,105.32 192.64,105.82
N17242608 on TOP: 139.78,125.76 138.91,125.76 138.68,125.53 138.68,123.57 138.75,123.51 139.53,123.51 139.61,123.58 139.61,124.14 139.83,124.36 139.83,125.72
N17243834 on TOP: 35.03,92.85 36.2,92.85 36.43,92.62 36.43,90.58 36.3,90.46 35.54,90.46 35.41,90.58 35.41,90.97 34.96,91.42 34.96,92.77
N17302218 on TOP: 101.58,86.01 102.47,86.01 103.1,85.38 103.1,83.98 102.98,83.85 102.22,83.85 102.09,83.98 102.09,84.36 101.45,85 101.45,85.89
N17303773 on TOP: 32.59,92.85 33.51,92.85 33.59,92.77 33.59,91.55 33.38,91.35 33.38,90.58 33.25,90.46 32.49,90.46 32.29,90.66 32.29,92.54
N17587353 on TOP: 210.85,125.92 212.03,125.92 212.21,125.74 212.21,125.13 211.92,124.84 210.84,124.84 210.74,124.94 210.74,125.8
N17587353 on TOP: 239.29,136.2 239.41,136.32 240.58,136.32 240.9,136.01 240.9,134.38 240.83,134.32 239.91,134.32 239.85,134.37 239.85,134.64 239.85,134.68 239.74,134.79 239.53,134.79 239.53,134.79 239.4,134.79 239.29,134.91
N17587353 on BOTTOM: 212.02,126.72 212.49,126.72 212.63,126.58 212.63,125.94 212.06,125.37 212.06,125.08 211.86,124.87 211.36,124.87 211.18,125.05 211.18,125.88
N17587353 on BOTTOM: 241.94,134.95 239.85,134.95 239.68,134.78 239.68,134.34 239.88,134.13 241.89,134.13 242,134.25 242,134.88
N17587375 on TOP (solid shape): 206.15,117.36 206.15,116.53 205.99,116.37 204.56,116.37 204.55,116.38 204.55,117.4 204.58,117.43 206.08,117.43
N17587375 on GND3 (solid shape): 205.15,117.65 205.15,116.53 205.01,116.39 204.55,116.39 203.81,117.14 203.81,117.5 204.16,117.86 204.94,117.86
N17587375 on TOP: 29.77,93.56 28.3,93.56 28.09,93.36 28.09,91.84 28.16,91.77 29.64,91.77 29.88,92.01 29.88,93.46
N17587375 on BOTTOM: 40.26,106.65 40.34,106.73 41.82,106.73 41.88,106.67 41.88,105.82 41.74,105.69 40.37,105.69 40.26,105.79
N17587375 on BOTTOM: 28.74,93.43 28.09,93.43 28.04,93.38 28.04,92.27 28.42,91.89 29.42,91.89 29.47,91.94 29.47,92.53 29.33,92.67 28.86,92.67 28.79,92.74 28.79,93.39
N17587375 on GND3: 40.28,107.33 40.98,107.33 41.05,107.26 41.05,105.93 40.8,105.68 40.5,105.68 40.25,105.93 40.25,107.3
N17587387 on TOP: 208.3,119.62 207.84,120.07 207.12,120.07 207.04,120.15 207.04,120.2 207.12,120.28 208.6,120.28 209.05,119.83 209.05,118.94 209,118.89 208.34,118.89 208.3,118.94
N17587389 on TOP: 209.82,118.62 209.98,118.78 209.98,119.94 209.24,120.68 207.12,120.68 207.04,120.61 207.04,120.56 207.12,120.48 208.54,120.48 209.15,119.87 209.15,118.78 209.31,118.62
N17587465 on TOP: 207.08,122.69 208.1,122.69 208.11,122.69 208.13,122.69 209.02,123.58 209.02,124.16 209.46,124.6 210.05,124.6 210.09,124.56 210.09,123.71 210.01,123.64 209.51,123.64 208.34,122.46 207.07,122.46 207.03,122.51 207.03,122.63
N17587467 on TOP: 207.1,123.09 208.07,123.09 208.47,123.49 208.47,125.18 209.04,125.74 209.04,125.74 210.04,125.74 210.1,125.67 210.1,124.96 210.05,124.91 209.43,124.91 208.83,124.31 208.83,123.53 208.14,122.84 207.11,122.84 207.02,122.93 207.02,123.01
N17744389 on TOP: 185.15,104.07 185.96,103.26 187.84,103.26 187.92,103.18 187.92,102.4 187.84,102.32 186.16,102.32 185.69,101.85 185.15,101.85 185.06,101.94 185.06,102.31 185.05,102.31 185.05,102.44 184.44,103.06 182.96,103.06 182.82,103.2 182.82,103.86 183.04,104.07
N19442543 on IN1 (solid shape): 77.9,148.59 77.9,146.03 77.51,145.65 70.92,145.65 70.75,145.83 70.75,148.7 70.97,148.93 77.55,148.93
N19639537 on TOP: 199.16,128.21 199.21,128.16 199.21,127.2 199.14,127.14 197.14,127.14 197.06,127.21 197.06,128.09 197.54,128.57 197.54,128.95 197.59,129 197.97,129 198.76,128.21
N19643413 on TOP: 38.55,86.01 36.68,86.01 36.56,86.14 36.56,86.84 36.68,86.97 37.75,86.97 37.87,87.08 38.58,87.08 38.67,87 38.67,86.13
N19643437 on TOP: 34.59,87.72 34.65,87.66 34.65,87.16 34.78,87.03 35.16,87.03 35.29,86.9 35.29,86.14 35.16,86.01 34.02,86.01 33.64,85.63 33.02,85.63 32.74,85.91 32.74,86.85 32.82,86.93 33.52,86.93 34.02,87.43 34.02,87.66 34.07,87.72
N20122392 on TOP: 191.62,142.4 192.51,142.4 192.67,142.25 193.43,142.25 193.5,142.17 193.5,142.04 193.43,141.97 192.79,141.97 192.21,141.38 191.62,141.38 191.5,141.51 191.5,142.27
N20122426 on TOP (solid shape): 193.94,141.33 193.94,140.55 193.27,139.89 193.27,139.1 193.15,138.97 192.39,138.97 192.26,139.1 192.26,139.86 193.15,140.75 193.61,140.75 193.68,140.83 193.68,141.11 193.63,141.16 193.63,141.36 193.71,141.44 193.83,141.44
N21077232 on TOP: 197.14,125.87 197.66,125.87 197.81,125.71 197.81,125.55 198.91,124.44 198.91,123.9 198.75,123.73 198.1,123.73 197.97,123.86 197.97,124.37 197.72,124.62 197.47,124.62 197.08,125 197.08,125.81
N21078155 on TOP: 194.54,125.89 195.56,125.89 195.69,125.76 195.69,124.75 195.94,124.49 195.94,123.86 195.69,123.6 194.67,123.6 194.42,123.86 194.42,125.76
N21234656 on TOP: 99.42,86.14 100.06,86.14 100.18,86.01 100.18,85 100.06,84.87 100.06,83.85 99.8,83.6 99.17,83.6 98.79,83.98 98.79,85.5
N22422694 on TOP (solid shape): 43.55,135.45 43.55,133.29 43.38,133.12 42.02,133.12 42.02,133.13 41.89,133.26 41.89,133.65 41.72,133.82 41.72,135.4 41.9,135.57 43.44,135.57
N23267569 on TOP (solid shape): 67.84,138.37 67.84,137.02 67.7,136.88 66.88,136.88 66.82,136.94 66.82,137.63 66.97,137.78 66.97,138.29 67.14,138.45 67.76,138.45
N24437699 on TOP: 92.11,100.17 93.99,100.17 94.07,100.09 94.07,99.1 93.99,99.02 92.24,99.02 92,99.26 92,100.05
N47519532 on TOP: 172.35,101.02 172.19,100.87 172.19,99.35 171.94,99.09 170.67,99.09 170.41,99.35 170.41,101.84 170.59,102.01 172.22,102.01 172.35,101.89
N51581707 on TOP: 192.77,133.13 193.78,133.13 193.91,133 193.91,131.1 193.66,130.84 192.77,130.84 192.51,131.1 192.51,132.49 192.64,132.62 192.64,133
N51584481 on TOP: 189.72,105.95 190.61,105.95 190.73,105.82 190.73,105.32 190.99,105.06 190.99,103.67 190.86,103.54 190.35,103.54 190.23,103.67 190.23,104.3 189.97,104.55 189.97,104.81 189.59,105.19 189.59,105.82
N51592304 on TOP: 236.53,134.68 238.61,134.68 238.82,134.47 238.82,133.66 238.68,133.53 236.67,133.53 236.4,133.79 236.4,134.55
N51600655 on TOP: 26.17,66.47 26.17,67.6 26.56,67.99 28.4,67.99 28.51,67.89 28.51,67.06 28.42,66.98 27.65,66.98 27.04,66.37 26.27,66.37
N51600691 on TOP: 26.16,64.93 26.16,63.97 26.24,63.88 28.37,63.88 28.53,64.04 28.53,64.87 28.39,65.01 26.23,65.01
N57436918 on TOP: 236.66,137.6 238.31,137.6 238.56,137.35 238.56,136.58 238.54,136.56 237.59,136.56 237.1,136.08 236.53,136.08 236.4,136.2 236.4,137.35
N57468046 on TOP: 103.47,95.23 104.22,95.23 104.29,95.17 104.29,94.14 104.5,93.92 105.07,93.92 105.12,93.87 105.12,93.43 105.09,93.39 103.57,93.39 103.32,93.65 103.32,95.08
N57468964 on TOP: 140.15,87.38 138.48,87.38 138.09,86.99 137.26,86.99 137.19,87.05 137.19,88.12 137.38,88.3 140.25,88.3 140.35,88.2 140.35,87.59
N57645204 on TOP: 141.97,130.08 142.22,129.83 142.22,127.32 141.9,127 141.28,127 141.21,127.07 141.21,128.26 141.03,128.44 141.03,128.93 140.95,129.01 140.95,129.96 140.95,129.97 141.06,130.08

Small or netless copper shapes (teardrops, artwork), in the pictures only: 33 on TOP, 19 on BOTTOM, 28 on IN1, 23 on GND1, 3 on IN2, 23 on GND4, 2 on VCC

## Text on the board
User.Comments: LA-C321P | Moopi_Wang | 2015-09-07 | 2016-09-07 | AAE00
Ref Des/Silkscreen Top: B | C | D | S7 | S5 | S6 | S4 | S3 | S2 | S1 | + | -
GND4: GND4
User.43: Width/Space | trace Width | 0_8mm_3+4+3(PTH L3-L8)(PP1086_2) (Top IN1 G-V IN2 G-V G-V IN3 G-V IN4 Bot)-150421.pdf | 3.3 | 3.5 | 6 | 3.1/44.7 | 3/45.51 | 5.5 | 3.1 | 3.6/2.4 | 3.3/3.1 | 6/7.3 | 3.5/5 | 2.6/3.2 | 2.6/4.5 | 4.4/5.8 | 90 ohm | L3/5 | L6/8 | L2 | L3 | L8 | L9 | 5.5/3 | 2.4 | 2.7/2.4 | L1/L3 | REF
User.45: FIGURE | SIZE | 4.0 | 8.0 | DRILL CHART: TOP to IN2 | ALL UNITS ARE IN MILS | DRILL CHART: TOP to IN1 | DRILL CHART: TOP to GND1 | DRILL CHART: IN3 to GND4 | DRILL CHART: IN1 to GND1 | DRILL CHART: IN1 to IN2 | DRILL CHART: GND1 to GND4 | DRILL CHART: IN3 to BOTTOM | DRILL CHART: GND1 to IN2 | TOLERANCE | +1.0/-1.0 | +3.0/-3.0 | PLATED | QTY | 1244 | 1596 | 3348 | 1 | 145 | 392 | 400 | 1710 | 490 | 583 | 10.0 | 16.0 | 20.0 | 47.0 | 51.0 | 181.0 | 205.0 | 28.0 | 45.0 | 65.0 | 47.0x16.0 | 57.0x24.0 | 63.0x24.0 | 91.0x51.0 | 37.0x28.0 | 79.0x16.0 | DRILL CHART: GND4 to VCC | DRILL CHART: VCC to BOTTOM | DRILL CHART: GND4 to BOTTOM | DRILL CHART: TOP to BOTTOM | +2.0/-2.0 | NON-PLATED | 97 | 104 | 781 | 24 | 1997 | 16 | 99 | 2 | 7 | 3 | 4 | 13
